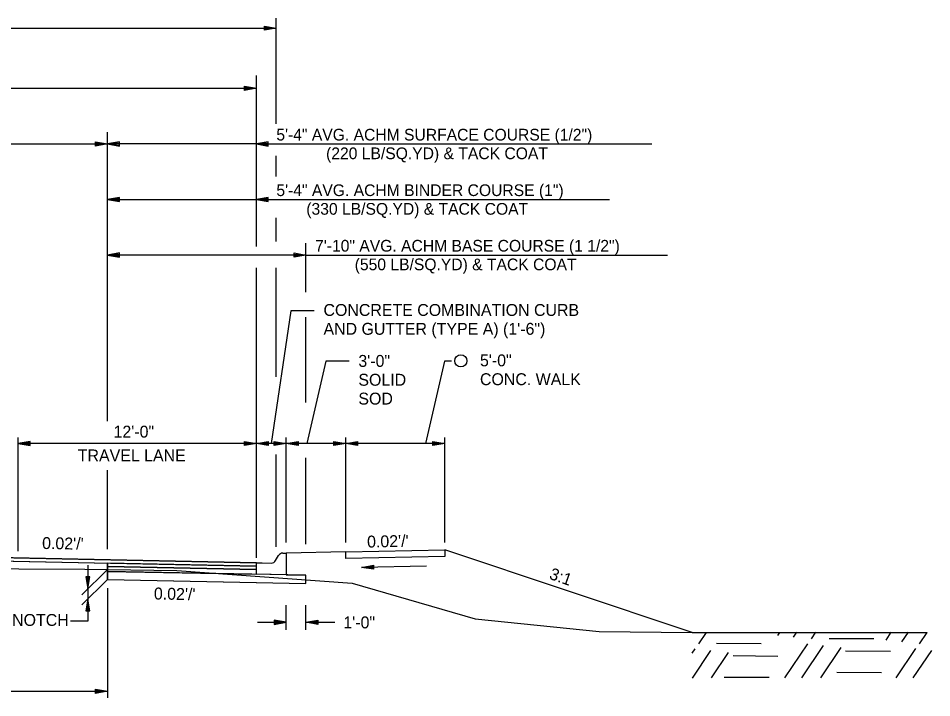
# Model space of a CAD drawing. Extents: x 1001270 to 1003428, y 1840152 to 1842912.
# Drawn here: x 1001356.57 to 1001402.6, y 1840216.69 to 1840250.95 of the extents above; entities that cross this region are included whole.
import ezdxf

# ---------------------------------------------------------------- set-up
doc = ezdxf.new("R2010")
doc.units = 0
for name, color, linetype in [('10', 7, 'Continuous'), ('19', 7, 'Continuous'), ('20', 7, 'Continuous'), ('8', 7, 'Continuous')]:
    doc.layers.add(name, color=color, linetype=linetype)

# ---------------------------------------------------------------- blocks, each defined once
blk = doc.blocks.new('TM')
at = {"layer": '8'}
for p, q in [((-120.309, 21.181), (-119.787, -20.829)), ((0, 0), (-120.309, 21.181)), ((-31.382, 2.945), (-120.176, 10.512)), ((-119.787, -20.829), (0, 0)), ((-119.911, -10.826), (-31.307, -3.057))]:
    blk.add_line(p, q, dxfattribs=at)

msp = doc.modelspace()

# ---------------------------------------------------------------- linework, layer by layer
at = {"layer": '10'}
msp.add_circle((1001378.87, 1840233.673), 0.306, dxfattribs=at)
at = {"layer": '19'}
for p, q in [((1001369.566, 1840245.631), (1001369.566, 1840250.946)), ((1001327.566, 1840250.444), (1001369.566, 1840250.444)), ((1001368.966, 1840250.339), (1001368.966, 1840250.549)), ((1001368.966, 1840250.549), (1001369.566, 1840250.444)), ((1001368.966, 1840250.494), (1001369.406, 1840250.459)), ((1001369.566, 1840250.444), (1001368.966, 1840250.339)), ((1001369.406, 1840250.429), (1001368.966, 1840250.389)), ((1001368.565, 1840239.443), (1001368.565, 1840248.068)), ((1001328.565, 1840247.417), (1001368.565, 1840247.417)), ((1001367.966, 1840247.312), (1001367.966, 1840247.522)), ((1001367.966, 1840247.522), (1001368.566, 1840247.417)), ((1001367.966, 1840247.467), (1001368.406, 1840247.432)), ((1001368.566, 1840247.417), (1001367.966, 1840247.312)), ((1001368.406, 1840247.402), (1001367.966, 1840247.362)), ((1001361.065, 1840230.638), (1001361.065, 1840245.208)), ((1001332.065, 1840244.61), (1001361.065, 1840244.61)), ((1001360.465, 1840244.505), (1001360.465, 1840244.715)), ((1001360.465, 1840244.715), (1001361.065, 1840244.61)), ((1001360.465, 1840244.66), (1001360.905, 1840244.625)), ((1001361.065, 1840244.61), (1001360.465, 1840244.505)), ((1001360.905, 1840244.595), (1001360.465, 1840244.555)), ((1001361.665, 1840244.713), (1001361.065, 1840244.608)), ((1001368.565, 1840244.608), (1001361.065, 1840244.608)), ((1001361.065, 1840244.608), (1001361.665, 1840244.503)), ((1001361.665, 1840244.658), (1001361.225, 1840244.623)), ((1001361.225, 1840244.593), (1001361.665, 1840244.553)), ((1001361.665, 1840244.503), (1001361.665, 1840244.713)), ((1001369.164, 1840244.713), (1001368.564, 1840244.608)), ((1001368.564, 1840244.608), (1001369.164, 1840244.503)), ((1001368.566, 1840244.608), (1001388.492, 1840244.608)), ((1001369.164, 1840244.658), (1001368.724, 1840244.623)), ((1001368.724, 1840244.593), (1001369.164, 1840244.553)), ((1001369.164, 1840244.503), (1001369.164, 1840244.713)), ((1001369.566, 1840242.962), (1001369.566, 1840244.005)), ((1001361.665, 1840241.914), (1001361.065, 1840241.809)), ((1001361.065, 1840241.809), (1001361.665, 1840241.704)), ((1001361.065, 1840241.808), (1001368.565, 1840241.808)), ((1001361.665, 1840241.859), (1001361.225, 1840241.824)), ((1001361.225, 1840241.794), (1001361.665, 1840241.754)), ((1001361.665, 1840241.704), (1001361.665, 1840241.914)), ((1001369.164, 1840241.913), (1001368.564, 1840241.808)), ((1001368.564, 1840241.808), (1001369.164, 1840241.703)), ((1001368.566, 1840241.808), (1001386.358, 1840241.808)), ((1001369.164, 1840241.858), (1001368.724, 1840241.823)), ((1001368.724, 1840241.793), (1001369.164, 1840241.753)), ((1001369.164, 1840241.703), (1001369.164, 1840241.913)), ((1001369.566, 1840239.694), (1001369.566, 1840240.891)), ((1001371.062, 1840237.134), (1001371.062, 1840239.61)), ((1001361.665, 1840239.114), (1001361.065, 1840239.009)), ((1001361.065, 1840239.009), (1001361.665, 1840238.904)), ((1001371.065, 1840239.008), (1001361.065, 1840239.008)), ((1001361.665, 1840239.059), (1001361.225, 1840239.024)), ((1001361.225, 1840238.994), (1001361.665, 1840238.954)), ((1001361.665, 1840238.904), (1001361.665, 1840239.114)), ((1001370.465, 1840238.903), (1001370.465, 1840239.113)), ((1001370.465, 1840239.113), (1001371.065, 1840239.008)), ((1001370.465, 1840239.058), (1001370.905, 1840239.023)), ((1001371.065, 1840239.008), (1001370.465, 1840238.903)), ((1001370.905, 1840238.993), (1001370.465, 1840238.953)), ((1001371.065, 1840239.008), (1001389.278, 1840239.008)), ((1001368.565, 1840223.738), (1001368.565, 1840238.372)), ((1001369.566, 1840232.864), (1001369.566, 1840238.369)), ((1001370.296, 1840236.199), (1001369.308, 1840229.507)), ((1001371.475, 1840236.199), (1001370.296, 1840236.199)), ((1001371.062, 1840231.583), (1001371.062, 1840235.871)), ((1001372.06, 1840233.664), (1001371.104, 1840229.507)), ((1001373.239, 1840233.664), (1001372.06, 1840233.664)), ((1001378.042, 1840233.664), (1001377.086, 1840229.507)), ((1001378.392, 1840233.664), (1001378.042, 1840233.664)), ((1001356.565, 1840224.082), (1001356.565, 1840229.807)), ((1001368.565, 1840223.738), (1001368.565, 1840229.807)), ((1001370.065, 1840224.516), (1001370.065, 1840229.807)), ((1001373.065, 1840224.516), (1001373.065, 1840229.807)), ((1001378.065, 1840224.516), (1001378.065, 1840229.807)), ((1001357.165, 1840229.612), (1001356.565, 1840229.507)), ((1001368.565, 1840229.507), (1001356.565, 1840229.507)), ((1001356.565, 1840229.507), (1001357.165, 1840229.402)), ((1001357.165, 1840229.557), (1001356.725, 1840229.522)), ((1001356.725, 1840229.492), (1001357.165, 1840229.452)), ((1001357.165, 1840229.402), (1001357.165, 1840229.612)), ((1001367.965, 1840229.402), (1001367.965, 1840229.612)), ((1001367.965, 1840229.612), (1001368.565, 1840229.507)), ((1001367.965, 1840229.557), (1001368.405, 1840229.522)), ((1001368.565, 1840229.507), (1001367.965, 1840229.402)), ((1001368.405, 1840229.492), (1001367.965, 1840229.452)), ((1001368.565, 1840229.507), (1001369.165, 1840229.612)), ((1001378.065, 1840229.507), (1001368.565, 1840229.507)), ((1001369.165, 1840229.402), (1001368.565, 1840229.507)), ((1001368.725, 1840229.522), (1001369.165, 1840229.557)), ((1001369.165, 1840229.452), (1001368.725, 1840229.492)), ((1001369.165, 1840229.612), (1001369.165, 1840229.402)), ((1001369.465, 1840229.402), (1001369.465, 1840229.612)), ((1001369.465, 1840229.612), (1001370.065, 1840229.507)), ((1001369.465, 1840229.557), (1001369.905, 1840229.522)), ((1001370.065, 1840229.507), (1001369.465, 1840229.402)), ((1001369.905, 1840229.492), (1001369.465, 1840229.452)), ((1001370.065, 1840229.507), (1001370.665, 1840229.612)), ((1001370.665, 1840229.402), (1001370.065, 1840229.507)), ((1001370.225, 1840229.522), (1001370.665, 1840229.557)), ((1001370.665, 1840229.452), (1001370.225, 1840229.492)), ((1001370.665, 1840229.612), (1001370.665, 1840229.402)), ((1001372.465, 1840229.402), (1001372.465, 1840229.612)), ((1001372.465, 1840229.612), (1001373.065, 1840229.507)), ((1001372.465, 1840229.557), (1001372.905, 1840229.522)), ((1001373.065, 1840229.507), (1001372.465, 1840229.402)), ((1001372.905, 1840229.492), (1001372.465, 1840229.452)), ((1001373.065, 1840229.507), (1001373.665, 1840229.612)), ((1001373.665, 1840229.402), (1001373.065, 1840229.507)), ((1001373.225, 1840229.522), (1001373.665, 1840229.557)), ((1001373.665, 1840229.452), (1001373.225, 1840229.492)), ((1001373.665, 1840229.612), (1001373.665, 1840229.402)), ((1001377.465, 1840229.402), (1001377.465, 1840229.612)), ((1001377.465, 1840229.612), (1001378.065, 1840229.507)), ((1001377.465, 1840229.557), (1001377.905, 1840229.522)), ((1001378.065, 1840229.507), (1001377.465, 1840229.402)), ((1001377.905, 1840229.492), (1001377.465, 1840229.452)), ((1001369.566, 1840224.307), (1001369.566, 1840228.957)), ((1001371.062, 1840224.426), (1001371.062, 1840228.791)), ((1001361.065, 1840224.18), (1001361.065, 1840228.17)), ((1001350.565, 1840223.858), (1001368.565, 1840223.498)), ((1001369.536, 1840223.607), (1001369.682, 1840223.859)), ((1001369.899, 1840223.983), (1001370.065, 1840223.983)), ((1001373.066, 1840224.043), (1001370.065, 1840223.983)), ((1001370.065, 1840223.983), (1001370.065, 1840223.649)), ((1001373.066, 1840224.043), (1001378.065, 1840224.143)), ((1001373.066, 1840223.71), (1001373.066, 1840224.043)), ((1001373.066, 1840224.043), (1001373.066, 1840224.043)), ((1001378.065, 1840223.81), (1001373.066, 1840223.71)), ((1001378.065, 1840224.143), (1001378.065, 1840223.81)), ((1001390.534, 1840219.987), (1001378.065, 1840224.143)), ((1001350.565, 1840223.691), (1001368.565, 1840223.331)), ((1001361.065, 1840222.648), (1001361.065, 1840223.481)), ((1001361.065, 1840223.314), (1001368.565, 1840223.164)), ((1001361.065, 1840223.314), (1001361.065, 1840223.064)), ((1001361.065, 1840223.314), (1001361.065, 1840223.314)), ((1001361.065, 1840223.314), (1001361.065, 1840223.314)), ((1001361.065, 1840223.314), (1001361.065, 1840223.314)), ((1001361.065, 1840223.314), (1001361.065, 1840223.314)), ((1001368.565, 1840223.498), (1001368.849, 1840223.492)), ((1001368.849, 1840223.492), (1001368.849, 1840223.492)), ((1001368.849, 1840223.492), (1001368.849, 1840223.492)), ((1001368.849, 1840223.492), (1001369.315, 1840223.483)), ((1001370.065, 1840223.649), (1001370.065, 1840223.468)), ((1001370.065, 1840223.468), (1001370.065, 1840222.888)), ((1001361.065, 1840223.157), (1001359.765, 1840221.884)), ((1001361.065, 1840223.064), (1001368.565, 1840222.914)), ((1001371.065, 1840222.868), (1001361.065, 1840223.064)), ((1001361.065, 1840223.064), (1001361.065, 1840222.648)), ((1001370.065, 1840222.888), (1001368.565, 1840222.918)), ((1001370.065, 1840222.888), (1001371.065, 1840222.868)), ((1001371.065, 1840222.448), (1001371.065, 1840222.868)), ((1001371.065, 1840222.868), (1001371.065, 1840222.868)), ((1001361.065, 1840222.648), (1001359.765, 1840221.375)), ((1001360.18, 1840222.788), (1001359.97, 1840222.788)), ((1001359.97, 1840222.788), (1001360.075, 1840222.188)), ((1001360.025, 1840222.788), (1001360.06, 1840222.348)), ((1001360.075, 1840222.188), (1001360.18, 1840222.788)), ((1001360.09, 1840222.348), (1001360.13, 1840222.788)), ((1001361.065, 1840222.648), (1001371.065, 1840222.448)), ((1001361.065, 1840222.648), (1001368.565, 1840222.498)), ((1001361.065, 1840222.648), (1001361.065, 1840222.648)), ((1001361.065, 1840222.213), (1001361.065, 1840216.692)), ((1001360.075, 1840221.679), (1001359.97, 1840221.079)), ((1001360.06, 1840221.519), (1001360.02, 1840221.079)), ((1001360.18, 1840221.079), (1001360.075, 1840221.679)), ((1001360.125, 1840221.079), (1001360.09, 1840221.519)), ((1001359.97, 1840221.079), (1001360.18, 1840221.079)), ((1001370.065, 1840220.118), (1001370.065, 1840221.357)), ((1001371.065, 1840220.118), (1001371.065, 1840221.357)), ((1001360.075, 1840220.55), (1001359.201, 1840220.55)), ((1001368.616, 1840220.497), (1001370.065, 1840220.497)), ((1001368.616, 1840220.497), (1001370.065, 1840220.497)), ((1001369.465, 1840220.602), (1001369.465, 1840220.392)), ((1001370.065, 1840220.497), (1001369.465, 1840220.602)), ((1001369.465, 1840220.602), (1001369.465, 1840220.392)), ((1001370.065, 1840220.497), (1001369.465, 1840220.602)), ((1001369.905, 1840220.512), (1001369.465, 1840220.547)), ((1001369.905, 1840220.512), (1001369.465, 1840220.547)), ((1001369.465, 1840220.392), (1001370.065, 1840220.497)), ((1001369.465, 1840220.392), (1001370.065, 1840220.497)), ((1001371.065, 1840220.497), (1001371.665, 1840220.602)), ((1001371.065, 1840220.497), (1001371.665, 1840220.602)), ((1001371.665, 1840220.392), (1001371.065, 1840220.497)), ((1001371.065, 1840220.497), (1001372.514, 1840220.497)), ((1001371.665, 1840220.392), (1001371.065, 1840220.497)), ((1001371.065, 1840220.497), (1001372.514, 1840220.497)), ((1001371.225, 1840220.512), (1001371.665, 1840220.547)), ((1001371.225, 1840220.512), (1001371.665, 1840220.547)), ((1001371.665, 1840220.602), (1001371.665, 1840220.392)), ((1001371.665, 1840220.602), (1001371.665, 1840220.392)), ((1001369.465, 1840220.442), (1001369.905, 1840220.482)), ((1001369.465, 1840220.442), (1001369.905, 1840220.482)), ((1001371.665, 1840220.442), (1001371.225, 1840220.482)), ((1001371.665, 1840220.442), (1001371.225, 1840220.482)), ((1001390.861, 1840219.404), (1001391.253, 1840219.987)), ((1001394.846, 1840219.838), (1001394.952, 1840219.988)), ((1001395.641, 1840219.746), (1001395.807, 1840219.99)), ((1001396.536, 1840219.654), (1001396.762, 1840219.993)), ((1001397.424, 1840219.683), (1001399.685, 1840219.672)), ((1001400.3, 1840219.598), (1001400.562, 1840219.994)), ((1001401.095, 1840219.506), (1001401.427, 1840219.995)), ((1001401.99, 1840219.414), (1001402.371, 1840219.988)), ((1001390.521, 1840218.936), (1001390.675, 1840219.161)), ((1001391.75, 1840219.443), (1001394.009, 1840219.421)), ((1001395.198, 1840217.691), (1001396.351, 1840219.412)), ((1001396.053, 1840217.693), (1001397.145, 1840219.32)), ((1001397.008, 1840217.695), (1001398.041, 1840219.228)), ((1001400.808, 1840217.696), (1001401.805, 1840219.172)), ((1001390.544, 1840217.687), (1001391.47, 1840219.069)), ((1001391.499, 1840217.689), (1001392.365, 1840218.977)), ((1001392.59, 1840218.814), (1001394.849, 1840218.792)), ((1001398.254, 1840219.055), (1001400.525, 1840219.042)), ((1001401.663, 1840217.699), (1001402.599, 1840219.08)), ((1001392.137, 1840217.734), (1001394.407, 1840217.722)), ((1001397.812, 1840217.985), (1001400.072, 1840217.963)), ((1001332.065, 1840217.019), (1001361.065, 1840217.019)), ((1001360.465, 1840216.914), (1001360.465, 1840217.124)), ((1001360.465, 1840217.124), (1001361.065, 1840217.019)), ((1001360.465, 1840217.069), (1001360.905, 1840217.034)), ((1001361.065, 1840217.019), (1001360.465, 1840216.914)), ((1001360.905, 1840217.004), (1001360.465, 1840216.964))]:
    msp.add_line(p, q, dxfattribs=at)
for points in [[(1001302.943, 1840229.121), (1001308.076, 1840228.81), (1001312.258, 1840228.16), (1001315.458, 1840226.988), (1001318.316, 1840225.539), (1001321.022, 1840223.767), (1001324.66, 1840222.838), (1001332.065, 1840222.904), (1001338.973, 1840223.085), (1001343.925, 1840223.174), (1001346.585, 1840223.234), (1001359.92, 1840223.173), (1001364.56, 1840223.108), (1001373.392, 1840222.461), (1001379.591, 1840220.668), (1001385.847, 1840220.033), (1001390.534, 1840219.987)], [(1001360.075, 1840223.375), (1001360.075, 1840220.55)], [(1001361.065, 1840223.064), (1001368.565, 1840222.914), (1001368.565, 1840223.164), (1001361.065, 1840223.314)], [(1001368.565, 1840222.918), (1001368.565, 1840223.081), (1001368.565, 1840223.331), (1001368.565, 1840223.498)], [(1001361.065, 1840222.648), (1001371.065, 1840222.448), (1001371.065, 1840222.868)], [(1001390.534, 1840219.987), (1001402.371, 1840219.988)]]:
    msp.add_lwpolyline(points, dxfattribs=at)
for points in [[(1001368.565, 1840223.498), (1001350.565, 1840223.858), (1001328.565, 1840223.418), (1001328.565, 1840223.251), (1001350.565, 1840223.691), (1001368.565, 1840223.331)], [(1001368.565, 1840223.331), (1001361.065, 1840223.481), (1001361.065, 1840223.314), (1001368.565, 1840223.164)]]:
    msp.add_lwpolyline(points, close=True, dxfattribs=at)
for centre, start, end in [((1001369.899, 1840223.733), 90, 149.8381), ((1001369.32, 1840223.733), 268.8542, 329.8365)]:
    msp.add_arc(centre, 0.25, start, end, dxfattribs=at)
at = {"layer": '20'}
msp.add_line((1001377.134, 1840223.328), (1001373.863, 1840223.263), dxfattribs=at)

# ---------------------------------------------------------------- block references
at = {"layer": '19', "xscale": 0.0050063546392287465, "yscale": -0.0050063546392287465, "rotation": -178.8781640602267}
msp.add_blockref('TM', (1001373.863, 1840223.261), dxfattribs=at)

# ---------------------------------------------------------------- texts
at = {"layer": '19'}
for s, height, p in [('5\'-4" AVG. ACHM SURFACE COURSE (1/2")', 0.59001, (1001369.57, 1840244.783)), ('(220 LB/SQ.YD) & TACK COAT', 0.59001, (1001372.077, 1840243.843)), ('5\'-4" AVG. ACHM BINDER COURSE (1")', 0.59001, (1001369.573, 1840241.983)), ('(330 LB/SQ.YD) & TACK COAT', 0.59001, (1001371.081, 1840241.043)), ('7\'-10" AVG. ACHM BASE COURSE (1 1/2")', 0.59001, (1001371.524, 1840239.183)), ('(550 LB/SQ.YD) & TACK COAT', 0.59001, (1001373.52, 1840238.243)), ('CONCRETE COMBINATION CURB', 0.6, (1001371.947, 1840235.94)), ('AND GUTTER (TYPE A) (1\'-6")', 0.6, (1001371.947, 1840234.99)), ('3\'-0"', 0.6, (1001373.705, 1840233.372)), ('5\'-0"', 0.6, (1001379.833, 1840233.4)), ('SOLID ', 0.6, (1001373.705, 1840232.422)), ('CONC. WALK', 0.6, (1001379.833, 1840232.45)), ('SOD', 0.6, (1001373.705, 1840231.472)), ('12\'-0"', 0.6, (1001361.368, 1840229.807)), ('TRAVEL LANE', 0.6, (1001359.565, 1840228.607)), ('NOTCH', 0.6, (1001356.255, 1840220.313))]:
    msp.add_text(s, height=height, dxfattribs=at).set_placement(p)
for s, rotation, p in [("0.02'/'", 358.8542, (1001357.762, 1840224.194)), ("0.02'/'", 1.1419, (1001374.15, 1840224.26)), ('3:1', 340.4943, (1001383.285, 1840222.698)), ("0.02'/'", 358.8542, (1001363.396, 1840221.65)), ('1\'-0"', 360, (1001372.949, 1840220.189))]:
    msp.add_text(s, height=0.6, rotation=rotation, dxfattribs=at).set_placement(p)

doc.saveas('drawing.dxf')
